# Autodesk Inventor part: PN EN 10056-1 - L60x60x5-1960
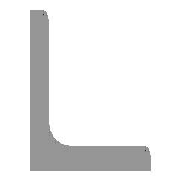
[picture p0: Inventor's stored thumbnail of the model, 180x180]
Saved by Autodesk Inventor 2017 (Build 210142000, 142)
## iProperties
IsCustomPart: 1
_CCFamilyMember: 130
_CCFamilyDisplayName: PN EN 10056-1 (Kątownik równoramienny) - Kątownik równoramienny
_FrameMemberDoc: Frame Member File
_Version: 15.0.0
_GetPNFromCC: 1
Created: 2016-02
Part Number: PN EN 10056-1 - L60x60x5-1960
Material: Stal, miękka
Description: Kątownik równoramienny
Document SubType Name: Modeling
Standard: PN
Designer: X
Standards Organization: PN
Language: pl-PL
Size Designation: L60x60x5
Categories: <MemberInstance><Categories><Category DisplayName="Kształtowniki konstrukcyjne" InternalName="089c4875-fa83-4c05-b084-43b9cc11f5ed" Mnemonic="GRDR"><CategoryPar
Stock Number: L60x60x5
Density: 7.85 g/cm^3
Appearance: Częściowo polerowana
G_W: 60,000 mm
G_H: 60,000 mm
G_L: 1960,000 mm
Author: X
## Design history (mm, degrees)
node "Płaszczyzna początkowa"
node "Płaszczyzna końcowa"
sketch "Szkic"
  geometry: L1 (-11.517, -3.517)-(-11.517, 39.483); L2 (-16.517, 43.483)-(-15.517, 43.483); L3 (-16.517, -16.517)-(-16.517, 43.483); L4 (-16.517, -16.517)-(43.483, -16.517); L5 (43.483, -15.517)-(43.483, -16.517); L6 (-3.517, -11.517)-(39.483, -11.517); L7 (0, 56.477)-(0, -28.683) reference; L8 (-28.683, 0)-(56.477, 0) reference; A1 r 8 centre (-3.517, -3.517) between (-11.517, -3.517) and (-3.517, -11.517); A2 r 4 centre (-15.517, 39.483) between (-11.517, 39.483) and (-15.517, 43.483); A3 r 4 centre (39.483, -15.517) between (43.483, -15.517) and (39.483, -11.517); 3 further points
  constraints: 12 end point, 6 point on circle, 6 point on line, 6 tangent, 3 centre point, 3 horizontal, 3 vertical, 1 equal radius
  dimensions: "d4" = 60 distance of L3.start L4.end (= b); "d6" = 60 distance of L3.start L2.start (= b); "d8" = 5 distance of point (43.483, -11.517) L4.end (= ParT); "d10" = 5 distance of L2.start point (-11.517, 43.483) (= ParT); "d17" = 8 radius of A1 (= R); "d18" = 4 radius of A2 (= R1); "d19" = 16.51748 distance between parallel lines of L8 L4 (= ex); "d20" = 16.51748 distance between parallel lines of L3 L7 (= d19)
extrude "Bryła" new body sketch "Szkic" stored distance "d11" = 1960 (= G_L); taper "d12" = 0 deg
node "Driven Length"
  sketch "Sketch3"
    geometry: L1 (0, 0)-(10, 0) reference
    constraints: 2 end point, 1 horizontal
  workplane "Work Plane10"
  sketch "Sketch4"
    geometry: L1 (-2, 0)-(12, 0) reference; L2 (-2, 1960)-(12, 1960) reference
    dimensions: "d24" = 1960 distance between parallel lines of L1 L2 (derived)
body "Solid1"
other parameters: "b" = 60 [user parameter; used in 3 equation terms], "ParT" = 5 [user parameter; used in 3 equation terms], "R" = 8 [user parameter; used in 1 equation term], "R1" = 4 [user parameter; used in 1 equation term], "G_L" = 1960 (= d24) [user parameter; used in 1 equation term], "d7" = 4 (derived), "d9" = 4 (derived), "ex" = 16.51748 (computed from b, ParT) [user parameter; used in 1 equation term], "G_OFFSET_START" = 0 [user parameter; used in 1 equation term], "G_OFFSET_END" = 0 [user parameter; used in 1 equation term], "d21" = 0 (computed from G_OFFSET_START), "d23" = 90 deg
